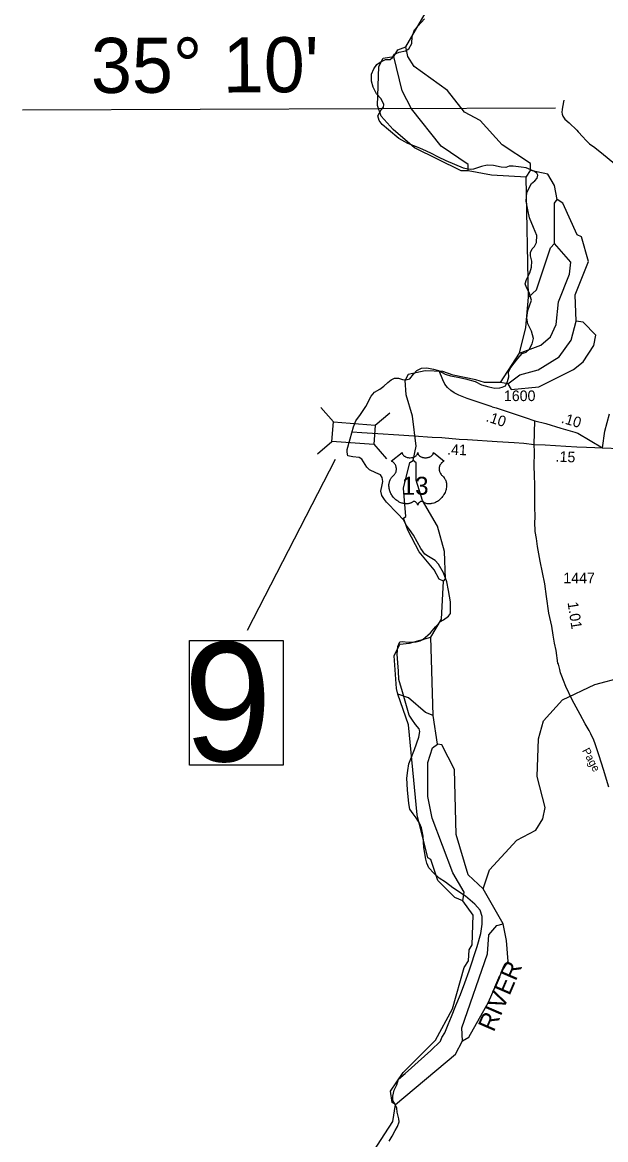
# Model space of a CAD drawing. Extents: x 2093524 to 2270757, y 289120 to 570408.
# Drawn here: x 2103792 to 2110673, y 503417 to 516601 of the extents above; entities that cross this region are included whole.
import ezdxf

# ---------------------------------------------------------------- set-up
doc = ezdxf.new("R2010")
doc.units = 0
for name, color, linetype in [('Exist Boundary Political CountyLine', 7, 'Continuous'), ('Exist Hydrographic Misc Water Feature', 7, 'Continuous'), ('Exist Hydrographic River Shore Label', 7, 'Continuous'), ('Exist Road Non-System Type 51', 7, 'Continuous'), ('Exist Road Primary US Attributed', 7, 'Continuous'), ('Exist Road Primary US Mileage Hundredths English Label', 7, 'Continuous'), ('Exist Road Primary US Shield CELL', 7, 'Continuous'), ('Exist Road Primary US Shield Number Label', 7, 'Continuous'), ('Exist Road Primary US Structure Standard Bridge CELL', 7, 'Continuous'), ('Exist Road Primary US Structure Standard Bridge Number Label', 7, 'Continuous'), ('Exist Road Secondary Mileage Hundredths English Label', 7, 'Continuous'), ('Exist Road Secondary Type 51 Attributed', 7, 'Continuous'), ('Exist Road Secondary Type 51 Label', 7, 'Continuous'), ('Exist Road Secondary Type 51 Number Label', 7, 'Continuous'), ('Map Preparation Longitude Latitude Label', 7, 'Continuous'), ('Map Preparation Longitude Latitude Lines', 7, 'Continuous')]:
    doc.layers.add(name, color=color, linetype=linetype)

msp = doc.modelspace()

# ---------------------------------------------------------------- linework, layer by layer
at = {"layer": 'Exist Boundary Political CountyLine'}
for points in [[(2109535, 514903), (2109497, 514887), (2109441, 514891), (2109349, 514913), (2109277, 514915), (2109208, 514900), (2109114, 514870), (2109084, 514864), (2109046, 514869), (2108998, 514882), (2108895, 514924), (2108792, 514966), (2108701, 515011), (2108610, 515057), (2108518, 515102), (2108463, 515125), (2108338, 515171), (2108235, 515231), (2108113, 515332), (2108038, 515397), (2108000, 515443), (2107984, 515499), (2108024, 515567), (2108054, 515601), (2108056, 515633), (2108026, 515699), (2107970, 515757), (2107930, 515837), (2107910, 515909), (2107912, 515989), (2107938, 516053), (2107972, 516105), (2108014, 516131), (2108076, 516161), (2108132, 516161), (2108158, 516187), (2108182, 516227), (2108238, 516251), (2108312, 516265), (2108352, 516289), (2108388, 516353), (2108392, 516433), (2108420, 516511), (2108538, 516641)], [(2108494, 510393), (2108407, 510548), (2108360, 510615), (2108323, 510662), (2108290, 510731), (2108218, 510806), (2108089, 510939), (2108064, 510971), (2108034, 511018), (2108020, 511068), (2108035, 511142), (2108044, 511182), (2108035, 511232), (2108019, 511262), (2107962, 511287), (2107888, 511321), (2107855, 511353), (2107795, 511447), (2107764, 511467), (2107692, 511473), (2107632, 511486), (2107623, 511530), (2107625, 511560), (2107660, 511687), (2107697, 511830), (2107726, 511898), (2107782, 511975), (2107846, 512069), (2107906, 512188), (2107946, 512236), (2108008, 512272), (2108058, 512306), (2108104, 512352), (2108142, 512382), (2108182, 512402), (2108230, 512402), (2108276, 512386), (2108317, 512382), (2108365, 512396), (2108405, 512450), (2108445, 512494), (2108501, 512520), (2108563, 512526), (2108643, 512508), (2108701, 512492), (2108781, 512450), (2108843, 512428), (2108929, 512416), (2109021, 512394), (2109132, 512362), (2109208, 512324), (2109294, 512300), (2109366, 512286), (2109426, 512288), (2109454, 512295), (2109493, 512312), (2109517, 512362), (2109531, 512418), (2109527, 512472), (2109545, 512518), (2109593, 512580), (2109639, 512636), (2109689, 512692), (2109734, 512710), (2109772, 512742), (2109806, 512808), (2109822, 512870), (2109800, 512958), (2109756, 513044), (2109744, 513113), (2109756, 513199), (2109799, 513324), (2109772, 513415), (2109740, 513473), (2109724, 513516), (2109739, 513568), (2109779, 513646), (2109799, 513714), (2109803, 513784), (2109785, 513846), (2109785, 513886), (2109806, 513930), (2109834, 513958), (2109856, 514002), (2109860, 514086), (2109822, 514180), (2109776, 514296), (2109754, 514390), (2109735, 514492), (2109745, 514592), (2109800, 514698), (2109836, 514730), (2109864, 514764), (2109874, 514796), (2109862, 514823), (2109827, 514845), (2109736, 514883), (2109677, 514891), (2109583, 514903), (2109535, 514903)], [(2108120, 503400), (2108154, 503456), (2108190, 503526), (2108218, 503572), (2108237, 503627), (2108235, 503664), (2108214, 503742), (2108211, 503789), (2108182, 503846), (2108161, 503880), (2108161, 503929), (2108179, 504000), (2108208, 504065), (2108230, 504130), (2108309, 504197), (2108384, 504265), (2108460, 504334), (2108535, 504402), (2108610, 504467), (2108723, 504580), (2108740, 504622), (2108777, 504679), (2108815, 504774), (2108853, 504870), (2108907, 504999), (2108962, 505128), (2109012, 505268), (2109062, 505410), (2109094, 505505), (2109127, 505600), (2109159, 505696), (2109202, 505849), (2109218, 505960), (2109218, 506050), (2109194, 506125), (2109130, 506196), (2109021, 506288), (2108869, 506387), (2108782, 506453), (2108710, 506504), (2108645, 506562), (2108586, 506625), (2108565, 506681), (2108550, 506726), (2108529, 506864), (2108522, 506996), (2108500, 507095), (2108478, 507153), (2108436, 507216), (2108401, 507263), (2108362, 507317), (2108353, 507382), (2108336, 507546), (2108329, 507682), (2108339, 507772), (2108352, 507850), (2108374, 507909), (2108420, 508022), (2108471, 508165), (2108482, 508231), (2108473, 508263), (2108428, 508316), (2108387, 508377), (2108356, 508427), (2108316, 508563), (2108276, 508699), (2108234, 508848), (2108228, 508944), (2108220, 509045), (2108212, 509146), (2108220, 509235), (2108244, 509291), (2108276, 509293), (2108344, 509289), (2108436, 509291), (2108484, 509301), (2108518, 509319), (2108605, 509399), (2108667, 509469), (2108725, 509529), (2108761, 509551), (2108821, 509593), (2108841, 509625), (2108841, 509675), (2108841, 509763), (2108818, 509898), (2108798, 509998), (2108760, 510105), (2108700, 510206), (2108661, 510249), (2108584, 510299), (2108542, 510326), (2108494, 510393)]]:
    msp.add_lwpolyline(points, dxfattribs=at)
at = {"layer": 'Exist Hydrographic Misc Water Feature'}
for p, q in [((2108048, 516180), (2108173, 516197)), ((2109735, 514774), (2109785, 514852)), ((2109764, 513360), (2109735, 514774)), ((2109434, 512350), (2109658, 512699)), ((2109143, 512382), (2108876, 512439)), ((2109518, 512335), (2109434, 512350)), ((2108361, 509274), (2108611, 509348)), ((2108639, 508422), (2108611, 509348)), ((2108244, 509263), (2108361, 509274)), ((2108690, 508083), (2108639, 508422)), ((2109463, 505962), (2109228, 506376))]:
    msp.add_line(p, q, dxfattribs=at)
for points in [[(2108314, 516312), (2108571, 516753), (2108554, 516812)], [(2108173, 516197), (2108222, 516278), (2108314, 516312)], [(2109785, 514852), (2109785, 514934), (2109451, 515157), (2109192, 515441), (2109008, 515540), (2108807, 515797), (2108415, 516080), (2108340, 516197), (2108314, 516312)], [(2109052, 514847), (2108969, 514849), (2108418, 515122), (2108167, 515337), (2108025, 515494), (2107983, 515620), (2107998, 516079), (2108048, 516180)], [(2109052, 514847), (2109051, 514923), (2108734, 515139), (2108383, 515579), (2108274, 515794), (2108173, 516197)], [(2109735, 514774), (2109327, 514799), (2109052, 514847)], [(2110103, 514511), (2110069, 514676), (2109993, 514808), (2109785, 514852)], [(2110071, 513993), (2110069, 514469), (2110103, 514511)], [(2110324, 513076), (2110314, 513385), (2110471, 513779), (2110387, 514069), (2110337, 514093), (2110169, 514467), (2110103, 514511)], [(2109658, 512699), (2109908, 512793), (2110024, 512892), (2110090, 513035), (2110115, 513304), (2110247, 513629), (2110263, 513770), (2110071, 513993)], [(2109764, 513360), (2109856, 513443), (2110021, 513942), (2110071, 513993)], [(2109658, 512699), (2109732, 513000), (2109764, 513360)], [(2109518, 512335), (2109659, 512443), (2109876, 512501), (2110125, 512654), (2110266, 512851), (2110324, 513076)], [(2109518, 512335), (2109560, 512268), (2109884, 512301), (2110292, 512503), (2110408, 512596), (2110533, 512787), (2110557, 512911), (2110407, 513062), (2110324, 513076)], [(2108876, 512439), (2108751, 512481), (2108543, 512489), (2108343, 512447), (2108310, 512379)], [(2108404, 511432), (2108437, 511599), (2108394, 511954), (2108319, 512205), (2108310, 512379)], [(2109434, 512350), (2109243, 512350), (2109143, 512382)], [(2108290, 510749), (2108315, 510771), (2108289, 511106), (2108363, 511407), (2108404, 511432)], [(2108759, 510008), (2108784, 510033), (2108774, 510358), (2108690, 510655), (2108514, 510957), (2108438, 511198), (2108438, 511405), (2108404, 511432)], [(2108759, 510008), (2108709, 510032), (2108650, 510141), (2108474, 510354), (2108340, 510607), (2108290, 510749)], [(2108611, 509348), (2108735, 509559), (2108759, 510008)], [(2108221, 508673), (2108204, 508739), (2108178, 509124), (2108244, 509263)], [(2109228, 506376), (2109303, 506601), (2109626, 506952), (2109851, 507069), (2109934, 507202), (2109958, 507336), (2109866, 507702), (2109881, 508145), (2109938, 508360), (2110163, 508605), (2110545, 508787), (2110870, 508873), (2111103, 508891), (2111353, 508791), (2111454, 508490), (2111530, 508292), (2111655, 508148), (2111797, 508093), (2112180, 508128)], [(2108639, 508422), (2108547, 508457), (2108346, 508632), (2108221, 508673)], [(2108987, 506234), (2108895, 506275), (2108695, 506476), (2108611, 506724), (2108577, 506741), (2108451, 507248), (2108347, 508313), (2108221, 508673)], [(2108987, 506234), (2109003, 506335), (2108870, 506567), (2108626, 507209), (2108575, 507466), (2108574, 507866), (2108632, 508042), (2108690, 508083)], [(2109228, 506376), (2109053, 506541), (2108910, 507016), (2108891, 507784), (2108740, 508076), (2108690, 508083)], [(2109064, 505658), (2109097, 505716), (2109112, 506067), (2108987, 506234)], [(2108984, 504584), (2108975, 504735), (2109281, 505611), (2109297, 505834), (2109388, 505944), (2109463, 505962)], [(2108984, 504584), (2109059, 504625), (2109291, 505037), (2109448, 505401), (2109523, 505518), (2109505, 505767), (2109463, 505962)], [(2109006, 505449), (2109056, 505527), (2109064, 505658)], [(2108136, 503990), (2108285, 504207), (2108667, 504590), (2108866, 504960), (2109006, 505449)], [(2108195, 503832), (2108901, 504425), (2108984, 504584)], [(2108195, 503832), (2108153, 503856), (2108136, 503990)], [(2106976, 502062), (2107051, 502103), (2107432, 502571), (2107930, 503273), (2108162, 503632), (2108195, 503832)]]:
    msp.add_lwpolyline(points, dxfattribs=at)
at = {"layer": 'Exist Road Non-System Type 51'}
msp.add_line((2110344, 511754), (2110637, 511582), dxfattribs=at)
for points in [[(2110178, 515684), (2110166, 515601), (2110162, 515573), (2110157, 515543), (2110159, 515517), (2110168, 515493), (2110190, 515460), (2110241, 515415), (2110333, 515329), (2110349, 515311), (2110405, 515252), (2110439, 515209), (2110482, 515166), (2110545, 515123), (2110649, 515041), (2110757, 514953), (2110856, 514871), (2111029, 514725)], [(2109336, 512066), (2109168, 512119), (2109041, 512161), (2108940, 512201), (2108885, 512231), (2108845, 512257), (2108806, 512294), (2108777, 512333), (2108754, 512383), (2108709, 512487)]]:
    msp.add_lwpolyline(points, dxfattribs=at)
at = {"layer": 'Exist Road Primary US Attributed'}
for points in [[(2110637, 511582), (2110844, 511572), (2111177, 511563), (2111343, 511573), (2111487, 511578), (2111664, 511599), (2111820, 511622), (2111971, 511657), (2112165, 511690), (2112386, 511740), (2112476, 511754), (2112508, 511761), (2112548, 511772), (2112582, 511782), (2112621, 511793), (2112667, 511806), (2112820, 511857), (2113146, 511960), (2113337, 512018), (2113470, 512068), (2113599, 512113), (2113718, 512149)], [(2107681, 511768), (2107795, 511761), (2107985, 511749), (2108233, 511732), (2108412, 511720), (2108626, 511706), (2108742, 511701), (2108946, 511683), (2109044, 511679), (2109395, 511654), (2109595, 511642), (2109707, 511634), (2109830, 511618)], [(2109830, 511618), (2109958, 511615), (2110202, 511600), (2110333, 511594), (2110447, 511589), (2110545, 511585), (2110637, 511582)]]:
    msp.add_lwpolyline(points, dxfattribs=at)
at = {"layer": 'Exist Road Primary US Shield CELL'}
msp.add_lwpolyline([(2108273, 511525), (2108273, 511520), (2108274, 511513), (2108275, 511510), (2108278, 511504), (2108283, 511496), (2108290, 511489), (2108298, 511483), (2108303, 511480), (2108312, 511475), (2108322, 511471), (2108333, 511468), (2108344, 511465), (2108356, 511464), (2108369, 511464), (2108382, 511465), (2108396, 511467), (2108403, 511469), (2108411, 511472), (2108418, 511475), (2108425, 511479), (2108431, 511483), (2108436, 511486), (2108443, 511493), (2108448, 511500), (2108451, 511503), (2108453, 511507), (2108455, 511515), (2108456, 511518), (2108457, 511525), (2108457, 511519), (2108458, 511516), (2108459, 511512), (2108460, 511508), (2108463, 511503), (2108466, 511498), (2108472, 511491), (2108475, 511488), (2108479, 511485), (2108487, 511479), (2108498, 511474), (2108503, 511472), (2108508, 511470), (2108514, 511468), (2108521, 511466), (2108528, 511465), (2108535, 511464), (2108542, 511464), (2108547, 511464), (2108554, 511464), (2108561, 511464), (2108567, 511465), (2108575, 511466), (2108580, 511467), (2108588, 511469), (2108595, 511472), (2108601, 511475), (2108609, 511479), (2108616, 511483), (2108620, 511487), (2108626, 511492), (2108631, 511498), (2108635, 511502), (2108637, 511507), (2108639, 511512), (2108640, 511517), (2108641, 511522), (2108641, 511525), (2108769, 511423), (2108766, 511422), (2108759, 511418), (2108754, 511415), (2108745, 511409), (2108741, 511405), (2108737, 511402), (2108734, 511398), (2108731, 511395), (2108727, 511389), (2108724, 511384), (2108720, 511378), (2108718, 511374), (2108714, 511363), (2108712, 511357), (2108711, 511351), (2108709, 511340), (2108709, 511334), (2108709, 511329), (2108709, 511323), (2108710, 511318), (2108711, 511312), (2108712, 511307), (2108713, 511301), (2108716, 511294), (2108719, 511287), (2108724, 511276), (2108732, 511264), (2108737, 511258), (2108743, 511252), (2108751, 511246), (2108755, 511242), (2108760, 511237), (2108768, 511227), (2108771, 511223), (2108774, 511218), (2108777, 511213), (2108781, 511208), (2108783, 511203), (2108787, 511192), (2108791, 511181), (2108792, 511175), (2108795, 511163), (2108796, 511157), (2108797, 511144), (2108797, 511129), (2108795, 511115), (2108793, 511099), (2108791, 511089), (2108787, 511077), (2108784, 511067), (2108778, 511053), (2108773, 511042), (2108766, 511030), (2108762, 511022), (2108756, 511014), (2108749, 511005), (2108741, 510995), (2108732, 510985), (2108724, 510977), (2108714, 510968), (2108708, 510963), (2108700, 510956), (2108688, 510948), (2108676, 510942), (2108666, 510937), (2108657, 510933), (2108646, 510928), (2108627, 510923), (2108620, 510922), (2108612, 510921), (2108604, 510920), (2108597, 510919), (2108587, 510919), (2108577, 510920), (2108567, 510921), (2108557, 510924), (2108547, 510927), (2108538, 510930), (2108528, 510935), (2108513, 510945), (2108508, 510947), (2108505, 510948), (2108499, 510948), (2108493, 510947), (2108488, 510945), (2108484, 510943), (2108479, 510940), (2108476, 510937), (2108471, 510933), (2108468, 510929), (2108466, 510926), (2108461, 510919), (2108460, 510916), (2108458, 510912), (2108457, 510905), (2108455, 510913), (2108452, 510919), (2108449, 510923), (2108447, 510927), (2108442, 510932), (2108438, 510936), (2108433, 510940), (2108428, 510943), (2108424, 510945), (2108420, 510947), (2108416, 510948), (2108412, 510948), (2108409, 510948), (2108404, 510947), (2108399, 510943), (2108393, 510939), (2108387, 510936), (2108380, 510932), (2108375, 510929), (2108368, 510927), (2108361, 510925), (2108353, 510922), (2108345, 510921), (2108338, 510920), (2108330, 510919), (2108323, 510919), (2108316, 510919), (2108309, 510919), (2108302, 510920), (2108292, 510922), (2108284, 510923), (2108275, 510926), (2108267, 510928), (2108257, 510932), (2108246, 510937), (2108237, 510941), (2108225, 510949), (2108210, 510959), (2108198, 510968), (2108190, 510976), (2108178, 510988), (2108170, 510996), (2108159, 511011), (2108152, 511021), (2108147, 511029), (2108140, 511042), (2108137, 511050), (2108132, 511061), (2108128, 511071), (2108125, 511081), (2108123, 511088), (2108121, 511099), (2108119, 511106), (2108118, 511117), (2108117, 511128), (2108117, 511139), (2108117, 511147), (2108118, 511158), (2108120, 511168), (2108122, 511177), (2108124, 511184), (2108126, 511192), (2108130, 511201), (2108134, 511210), (2108138, 511217), (2108143, 511224), (2108148, 511231), (2108155, 511238), (2108162, 511244), (2108168, 511249), (2108176, 511257), (2108179, 511261), (2108184, 511267), (2108188, 511273), (2108191, 511278), (2108195, 511286), (2108197, 511291), (2108200, 511300), (2108201, 511306), (2108203, 511314), (2108204, 511321), (2108204, 511330), (2108204, 511338), (2108203, 511347), (2108201, 511355), (2108199, 511363), (2108196, 511371), (2108193, 511378), (2108188, 511386), (2108183, 511394), (2108177, 511400), (2108172, 511406), (2108166, 511410), (2108161, 511414), (2108154, 511418), (2108148, 511421), (2108144, 511423)], close=True, dxfattribs=at)
at = {"layer": 'Exist Road Primary US Structure Standard Bridge CELL'}
for p, q in [((2107314, 512058), (2107461, 511886)), ((2107955, 511847), (2108127, 511995)), ((2107272, 511508), (2107444, 511655)), ((2107938, 511622), (2108086, 511450))]:
    msp.add_line(p, q, dxfattribs=at)
msp.add_lwpolyline([(2107461, 511886), (2107955, 511848), (2107938, 511618), (2107444, 511655)], close=True, dxfattribs=at)
at = {"layer": 'Exist Road Primary US Structure Standard Bridge Number Label'}
msp.add_line((2107481, 511443), (2106443, 509424), dxfattribs=at)
msp.add_lwpolyline([(2105764, 509308), (2106867, 509308), (2106867, 507835), (2105764, 507835)], close=True, dxfattribs=at)
at = {"layer": 'Exist Road Secondary Type 51 Attributed'}
msp.add_line((2109830, 511618), (2109836, 511897), dxfattribs=at)
for points in [[(2109336, 512066), (2109383, 512051), (2109725, 511940), (2109836, 511897)], [(2110637, 511582), (2110665, 511777), (2110720, 511982)], [(2109836, 511897), (2109967, 511867), (2110146, 511811), (2110309, 511764), (2110344, 511754)], [(2110709, 507576), (2110647, 507785), (2110598, 507944), (2110570, 508027), (2110546, 508099), (2110527, 508150), (2110509, 508178), (2110498, 508204), (2110478, 508243), (2110432, 508322), (2110372, 508435), (2110280, 508607), (2110203, 508762), (2110174, 508833), (2110155, 508887), (2110142, 508925), (2110131, 508964), (2110118, 509026), (2110110, 509038), (2110089, 509187), (2110071, 509277), (2110053, 509371), (2110037, 509476), (2110004, 509630), (2109974, 509827), (2109955, 509977), (2109899, 510242), (2109870, 510415), (2109858, 510509), (2109842, 510591), (2109840, 510623), (2109837, 510674), (2109840, 510783), (2109837, 510869), (2109837, 510979), (2109837, 511135), (2109835, 511262), (2109831, 511360), (2109833, 511534), (2109830, 511618)]]:
    msp.add_lwpolyline(points, dxfattribs=at)
at = {"layer": 'Map Preparation Longitude Latitude Lines'}
msp.add_line((2103792, 515567), (2110081, 515591), dxfattribs=at)

# ---------------------------------------------------------------- texts
at = {"layer": 'Exist Hydrographic River Shore Label'}
msp.add_text('RIVER', height=210, rotation=66.6993, dxfattribs=at).set_placement((2109353, 504678))
at = {"layer": 'Exist Road Primary US Mileage Hundredths English Label'}
for s, rotation, p in [('.41', 357.7181, (2108801, 511501)), ('.15', 357.4984, (2110081, 511418))]:
    msp.add_text(s, height=125, rotation=rotation, dxfattribs=at).set_placement(p)
at = {"layer": 'Exist Road Primary US Shield Number Label'}
msp.add_text('13', height=212.5, dxfattribs=at).set_placement((2108268, 511026))
at = {"layer": 'Exist Road Primary US Structure Standard Bridge Number Label'}
msp.add_text('9', height=1400, dxfattribs=at).set_placement((2105694, 507882))
at = {"layer": 'Exist Road Secondary Mileage Hundredths English Label'}
for s, rotation, p in [('.10', 342.0236, (2109253, 511896)), ('.10', 343.8183, (2110141, 511878)), ('1.01', 278.7041, (2110223, 509755))]:
    msp.add_text(s, height=125, rotation=rotation, dxfattribs=at).set_placement(p)
at = {"layer": 'Exist Road Secondary Type 51 Label'}
msp.add_text('Page', height=95, rotation=297.8463, dxfattribs=at).set_placement((2110393, 508009))
at = {"layer": 'Exist Road Secondary Type 51 Number Label'}
for s, p in [('1600', (2109473, 512132)), ('1447', (2110174, 509982))]:
    msp.add_text(s, height=125, dxfattribs=at).set_placement(p)
at = {"layer": 'Map Preparation Longitude Latitude Label'}
msp.add_text("35° 10'", height=650, rotation=0.2164, dxfattribs=at).set_placement((2104602, 515767))

doc.saveas('drawing.dxf')
